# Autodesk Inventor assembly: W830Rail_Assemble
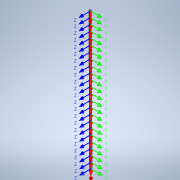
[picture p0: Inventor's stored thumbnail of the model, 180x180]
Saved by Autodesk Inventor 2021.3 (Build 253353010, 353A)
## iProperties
Created: 2021-11
Part Number: W830Rail_Assemble
Document SubType Name: Assembly
Designer: u1426
Author: u1426
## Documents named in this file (5)
- S:\Bridge_CADD\Other\SampleBridgeInventor\W830Rail_Assemble.iam
- S:\Bridge_CADD\Other\SampleBridgeInventor\W830Curb.ipt
- S:\Bridge_CADD\Other\SampleBridgeInventor\AISC - 6 x 3 x 1_4 - 125 - End.ipt
- S:\Bridge_CADD\Other\SampleBridgeInventor\AISC - 6 x 4 x 1_4 - 125 - End.ipt
- S:\Bridge_CADD\Other\SampleBridgeInventor\W830Post-Slab.iam
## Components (29 placed, 4 different names)
1. W830Curb:1 — Mate:3, Mate:4, Flush:1, Mate:5, Mate:6, Flush:2, Mate:7, Mate:8, Flush:3, Mate:9, Mate:10, Flush:4, Mate:16, Mate:17, Mate:18, Flush:7, Mate:19, Mate:20, Mate:21, Mate:22
2. AISC - 6 x 3 x 1_4 - 125 - End:1 — Mate:3, Mate:4, Flush:1
3. AISC - 6 x 3 x 1_4 - 125 - End:2 — Mate:7, Mate:8, Flush:3
4. AISC - 6 x 4 x 1_4 - 125 - End:1 — Mate:5, Mate:6, Flush:2
5. AISC - 6 x 4 x 1_4 - 125 - End:2 — Mate:9, Mate:10, Flush:4
6. W830Post-Slab:1 [sub-assembly] — Mate:16, Mate:19, Mate:22
7. W830Post-Slab:2 [sub-assembly]
8. W830Post-Slab:3 [sub-assembly]
9. W830Post-Slab:4 [sub-assembly]
10. W830Post-Slab:5 [sub-assembly]
11. W830Post-Slab:6 [sub-assembly]
12. W830Post-Slab:7 [sub-assembly]
13. W830Post-Slab:8 [sub-assembly]
14. W830Post-Slab:9 [sub-assembly]
15. W830Post-Slab:10 [sub-assembly]
16. W830Post-Slab:11 [sub-assembly]
17. W830Post-Slab:12 [sub-assembly]
18. W830Post-Slab:13 [sub-assembly]
19. W830Post-Slab:14 [sub-assembly]
20. W830Post-Slab:15 [sub-assembly]
21. W830Post-Slab:16 [sub-assembly]
22. W830Post-Slab:17 [sub-assembly]
23. W830Post-Slab:18 [sub-assembly]
24. W830Post-Slab:19 [sub-assembly]
25. W830Post-Slab:20 [sub-assembly]
26. W830Post-Slab:21 [sub-assembly]
27. W830Post-Slab:25 [sub-assembly]
28. W830Post-Slab:23 [sub-assembly] — Flush:8, Mate:20, Mate:21
29. W830Post-Slab:24 [sub-assembly]
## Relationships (21: Mate 15, Flush 6)
- Mate:3: W830Curb:1 ↔ AISC - 6 x 3 x 1_4 - 125 - End:1
- Mate:4: W830Curb:1 ↔ AISC - 6 x 3 x 1_4 - 125 - End:1
- Flush:1: W830Curb:1 ↔ AISC - 6 x 3 x 1_4 - 125 - End:1
- Mate:5: W830Curb:1 ↔ AISC - 6 x 4 x 1_4 - 125 - End:1
- Mate:6: W830Curb:1 ↔ AISC - 6 x 4 x 1_4 - 125 - End:1
- Flush:2: W830Curb:1 ↔ AISC - 6 x 4 x 1_4 - 125 - End:1
- Mate:7: W830Curb:1 ↔ AISC - 6 x 3 x 1_4 - 125 - End:2
- Mate:8: W830Curb:1 ↔ AISC - 6 x 3 x 1_4 - 125 - End:2
- Flush:3: W830Curb:1 ↔ AISC - 6 x 3 x 1_4 - 125 - End:2
- Mate:9: W830Curb:1 ↔ AISC - 6 x 4 x 1_4 - 125 - End:2
- Mate:10: W830Curb:1 ↔ AISC - 6 x 4 x 1_4 - 125 - End:2
- Flush:4: W830Curb:1 ↔ AISC - 6 x 4 x 1_4 - 125 - End:2
- Mate:16: W830Curb:1 ↔ W830Post-Slab:1
- Mate:17: W830Curb:1
- Mate:18: W830Curb:1
- Flush:7: W830Curb:1
- Mate:19: W830Curb:1 ↔ W830Post-Slab:1
- Flush:8: W830Post-Slab:23
- Mate:20: W830Curb:1 ↔ W830Post-Slab:23
- Mate:21: W830Curb:1 ↔ W830Post-Slab:23
- Mate:22: W830Curb:1 ↔ W830Post-Slab:1
